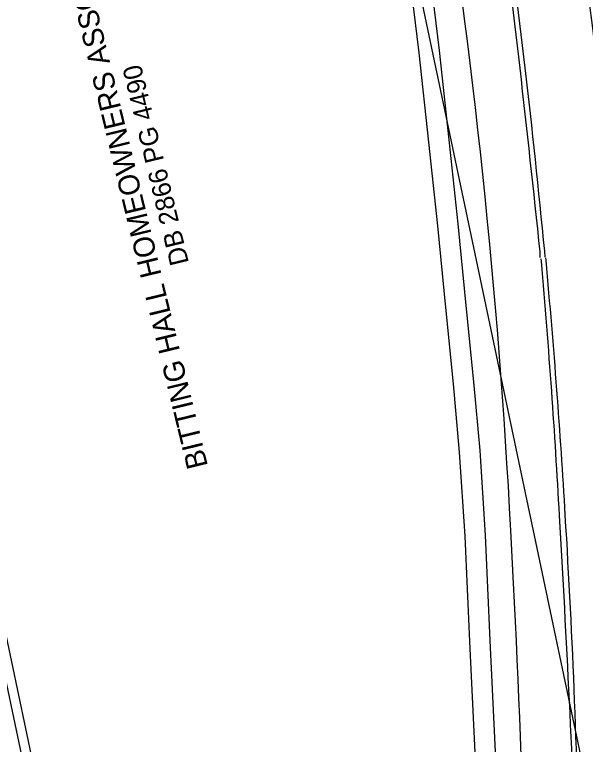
# Model space of a CAD drawing. Extents: x 1611576 to 1617186, y 899279 to 905462.
# Drawn here: x 1616538.9 to 1616674.8, y 902318 to 902491.7 of the extents above; entities that cross this region are included whole.
import ezdxf

# ---------------------------------------------------------------- set-up
doc = ezdxf.new("R2010")
doc.units = 0
for name, color, linetype in [('Exist Horizontal Alignment', 7, 'Continuous'), ('Exist Property Deed Book Text', 7, 'Continuous'), ('Exist Property Owner Text', 7, 'Continuous'), ('Exist Right of Way Line', 7, 'Continuous'), ('Exist Roads EOP', 7, 'Continuous'), ('Exist Roads EOP Other', 7, 'Continuous'), ('Exist Roads EOT', 7, 'Continuous'), ('Prop OH Tel Lines', 7, 'Continuous')]:
    doc.layers.add(name, color=color, linetype=linetype)

msp = doc.modelspace()

# ---------------------------------------------------------------- linework, layer by layer
at = {"layer": 'Exist Horizontal Alignment'}
msp.add_arc((1615052.19, 902285.31), 1637.02, 2.98333, 9.05, dxfattribs=at)
at = {"layer": 'Exist Right of Way Line'}
for p, q in [((1616010.65, 905462.23), (1616993.32, 900797.76)), ((1615887.44, 905426.15), (1616864.55, 900788.06)), ((1616657.69, 902356.37), (1616657.04, 902368.94))]:
    msp.add_line(p, q, dxfattribs=at)
for centre, radius, start, end in [((1615052.19, 902285.31), 1607.02, 2.98333, 9.05), ((1614235.45, 902230.14), 2425.53, 356.08333, 2.98333)]:
    msp.add_arc(centre, radius, start, end, dxfattribs=at)
at = {"layer": 'Exist Roads EOP'}
for p, q in [((1616664.06, 902433.91), (1616664.02, 902435.24)), ((1616664.33, 902433.03), (1616664.3, 902433.61))]:
    msp.add_line(p, q, dxfattribs=at)
for points in [[(1616664.02, 902435.24), (1616659.23, 902479.02), (1616653.86, 902521.19), (1616647.48, 902561.19), (1616640.05, 902603.13), (1616633.52, 902638.17), (1616624.95, 902680.56), (1616615.82, 902721.84), (1616606.01, 902763.05), (1616595.75, 902801.7), (1616584.26, 902841.93), (1616572.3, 902881.24), (1616564.26, 902906.37), (1616556.43, 902931.12), (1616543.99, 902967.9), (1616530.08, 903008.97), (1616517.05, 903047.39)], [(1616607.54, 902891.47), (1616619.8, 902851.65), (1616630.95, 902811.11), (1616641.26, 902771.18), (1616651.06, 902730.14), (1616660.51, 902687.43), (1616669.23, 902644.79), (1616673.27, 902623.83), (1616676.02, 902609.12), (1616683.43, 902567.11), (1616690.02, 902525.73), (1616695.57, 902482.82), (1616700.47, 902437.88)], [(1616655.28, 901931.6), (1616660.06, 901975.76), (1616663.88, 902018.68), (1616667.04, 902062.5), (1616670.01, 902105.53), (1616671.54, 902149.52), (1616672.6, 902193.68), (1616673.08, 902239.26), (1616672.8, 902282.74), (1616671, 902328.37), (1616668.63, 902372.54), (1616666.77, 902402.14), (1616664.33, 902433.03)]]:
    msp.add_spline(points, degree=3, dxfattribs=at)
at = {"layer": 'Exist Roads EOP Other'}
for points in [[(1616653.39, 902316.3), (1616652.13, 902342.73), (1616651.02, 902367.82), (1616649.72, 902387.98), (1616648.26, 902404.34), (1616646.41, 902422.47), (1616644.51, 902441.92), (1616642.39, 902461.9), (1616640.05, 902483.2), (1616636.84, 902509.29), (1616633.58, 902532.38), (1616630.01, 902555.58), (1616625.98, 902581.04), (1616621.66, 902605.52), (1616617.03, 902630.01), (1616612.92, 902650.99), (1616607.66, 902676.06), (1616602.92, 902697.58), (1616597.72, 902719.72), (1616593.76, 902736.26), (1616588.99, 902755.56)], [(1616648.51, 902316.11), (1616647.25, 902342.52), (1616646.14, 902367.57), (1616644.85, 902387.63), (1616643.4, 902403.89), (1616641.55, 902422), (1616639.65, 902441.45), (1616637.53, 902461.4), (1616635.2, 902482.65), (1616632, 902508.68), (1616628.75, 902531.69), (1616625.18, 902554.85), (1616621.17, 902580.26), (1616616.86, 902604.66), (1616612.24, 902629.12), (1616608.13, 902650.05), (1616602.88, 902675.06), (1616598.15, 902696.53), (1616592.96, 902718.62), (1616589.01, 902735.14), (1616584.24, 902754.42)]]:
    msp.add_lwpolyline(points, dxfattribs=at)
at = {"layer": 'Exist Roads EOT'}
for p, q in [((1616665.2, 902434.04), (1616665.13, 902435.43)), ((1616665.45, 902433.28), (1616665.41, 902433.83))]:
    msp.add_line(p, q, dxfattribs=at)
for points in [[(1616665.13, 902435.43), (1616660.48, 902479.08), (1616654.89, 902521.26), (1616648.51, 902561.33), (1616641.12, 902603.28), (1616634.46, 902638.28), (1616625.9, 902680.69), (1616616.67, 902721.99), (1616606.86, 902763.22), (1616596.71, 902801.99), (1616585.45, 902842.18), (1616573.19, 902881.5), (1616565.19, 902906.61), (1616557.25, 902931.31), (1616544.89, 902968.22), (1616530.94, 903009.35), (1616518.06, 903047.65)], [(1616657.03, 901931.53), (1616661.72, 901975.47), (1616665.32, 902018.62), (1616668.31, 902062.36), (1616670.59, 902105.52), (1616672.4, 902149.47), (1616673.48, 902193.66), (1616673.75, 902239.27), (1616673.47, 902282.77), (1616672.23, 902328.42), (1616670.01, 902372.56), (1616668.01, 902402.36), (1616665.45, 902433.28)]]:
    msp.add_spline(points, degree=3, dxfattribs=at)
at = {"layer": 'Prop OH Tel Lines'}
msp.add_line((1616578.22, 902137.47), (1616526.22, 902383.26), dxfattribs=at)

# ---------------------------------------------------------------- texts
at = {"layer": 'Exist Property Deed Book Text'}
msp.add_text('DB 2866 PG 4490', height=4.5, rotation=103.6417, dxfattribs=at).set_placement((1616580.4, 902432.67))
at = {"layer": 'Exist Property Owner Text'}
msp.add_text('BITTING HALL HOMEOWNERS ASSOCIATION INC.', height=5, rotation=103.6417, dxfattribs=at).set_placement((1616584.93, 902384.3))

doc.saveas('drawing.dxf')
